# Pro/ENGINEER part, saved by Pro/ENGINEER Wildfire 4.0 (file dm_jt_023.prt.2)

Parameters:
  METRIC = "NO"

Other parameters: PITCH, DRILL_DIAMETER, THREAD_DIAMETER, THREADS_PER_INCH, CBORE_DIAMETER, CBORE_DEPTH, DRILL_POINT_ANGLE, DRILL_DEPTH, THREAD_DEPTH, THREAD_LENGTH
